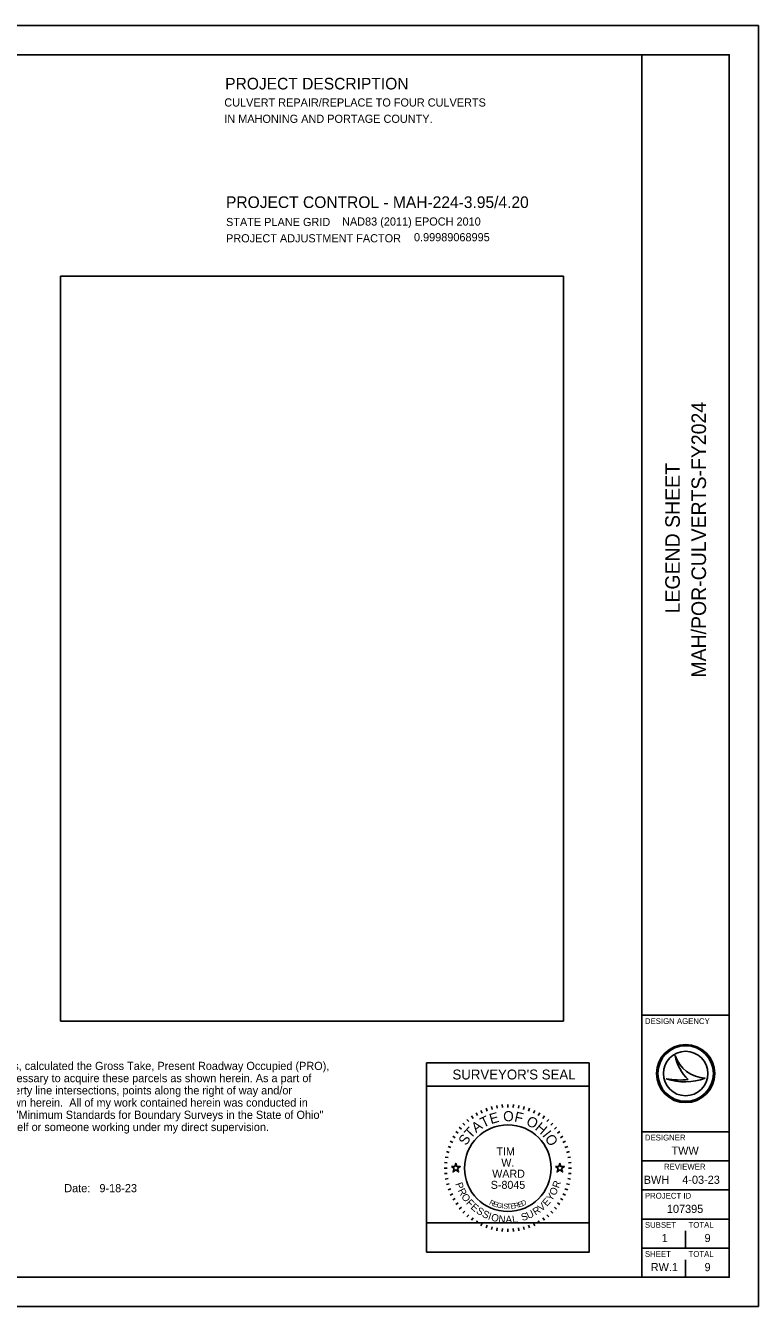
# Model space of a CAD drawing. Extents: x 0 to 34, y 0 to 22.
# Drawn here: x 21.41 to 34, y 0 to 22 of the extents above; entities that cross this region are included whole.
import ezdxf

# ---------------------------------------------------------------- set-up
doc = ezdxf.new("R2010")
doc.units = 0
for name, color, linetype in [('Default', 7, 'Continuous'), ('SH_Border', 7, 'Continuous'), ('SH_Cut_Line', 7, 'Continuous'), ('SH_Data', 7, 'Continuous'), ('SH_Text', 7, 'Continuous')]:
    doc.layers.add(name, color=color, linetype=linetype)

msp = doc.modelspace()

# ---------------------------------------------------------------- linework, layer by layer
at = {"layer": 'Default'}
for points in [[(28.725, 2.4), (28.783, 2.4), (28.801, 2.456), (28.82, 2.4), (28.878, 2.4), (28.831, 2.366), (28.849, 2.31), (28.801, 2.344), (28.754, 2.31), (28.772, 2.366)], [(30.512, 2.4), (30.571, 2.4), (30.589, 2.456), (30.607, 2.4), (30.666, 2.4), (30.618, 2.366), (30.636, 2.31), (30.589, 2.344), (30.542, 2.31), (30.56, 2.366)]]:
    msp.add_lwpolyline(points, close=True, dxfattribs=at)
at = {"layer": 'SH_Border'}
for p, q in [((32, 0.5), (32, 21.5)), ((32, 5), (33.5, 5)), ((32, 3), (33.5, 3)), ((32, 2.5), (33.5, 2.5)), ((32, 2), (33.5, 2)), ((32, 1.5), (33.5, 1.5)), ((32, 1), (33.5, 1))]:
    msp.add_line(p, q, dxfattribs=at)
msp.add_lwpolyline([(1.5, 21.5), (33.5, 21.5), (33.5, 0.5), (1.5, 0.5)], close=True, dxfattribs=at)
at = {"layer": 'SH_Cut_Line'}
msp.add_lwpolyline([(0, 0), (34, 0), (34, 22), (0, 22)], close=True, dxfattribs=at)
at = {"layer": 'SH_Data'}
for p, q in [((28.295, 0.933), (28.295, 4.183)), ((28.295, 4.183), (31.095, 4.183)), ((31.095, 4.183), (31.095, 0.933)), ((32.567, 4.31), (32.567, 4.31)), ((32.75, 4), (32.75, 4)), ((28.295, 3.783), (31.095, 3.783)), ((32.417, 3.91), (32.417, 3.91)), ((33.087, 3.919), (33.087, 3.919)), ((29.148, 3.322), (29.173, 3.279)), ((29.233, 3.366), (29.254, 3.321)), ((29.321, 3.403), (29.338, 3.356)), ((29.412, 3.432), (29.425, 3.383)), ((29.505, 3.452), (29.514, 3.403)), ((29.6, 3.465), (29.604, 3.415)), ((29.695, 3.469), (29.695, 3.419)), ((29.791, 3.465), (29.786, 3.415)), ((29.885, 3.452), (29.876, 3.403)), ((29.978, 3.432), (29.965, 3.383)), ((30.069, 3.403), (30.052, 3.356)), ((30.157, 3.366), (30.136, 3.321)), ((30.242, 3.322), (30.217, 3.279)), ((28.922, 3.148), (28.957, 3.113)), ((28.992, 3.213), (29.024, 3.175)), ((29.068, 3.271), (29.097, 3.23)), ((30.323, 3.271), (30.294, 3.23)), ((30.398, 3.213), (30.366, 3.175)), ((30.469, 3.148), (30.433, 3.113)), ((28.748, 2.922), (28.791, 2.897)), ((28.799, 3.002), (28.84, 2.974)), ((28.857, 3.078), (28.896, 3.046)), ((30.533, 3.078), (30.495, 3.046)), ((30.591, 3.002), (30.55, 2.974)), ((30.642, 2.922), (30.599, 2.897)), ((28.639, 2.658), (28.687, 2.645)), ((28.667, 2.749), (28.714, 2.732)), ((28.704, 2.837), (28.749, 2.816)), ((30.686, 2.837), (30.641, 2.816)), ((30.723, 2.749), (30.676, 2.732)), ((30.752, 2.658), (30.703, 2.645)), ((28.606, 2.47), (28.655, 2.466)), ((28.618, 2.565), (28.667, 2.556)), ((30.772, 2.565), (30.723, 2.556)), ((30.785, 2.47), (30.735, 2.466)), ((28.601, 2.375), (28.651, 2.375)), ((28.606, 2.28), (28.655, 2.284)), ((30.785, 2.28), (30.735, 2.284)), ((30.789, 2.375), (30.739, 2.375)), ((28.618, 2.185), (28.667, 2.194)), ((28.639, 2.092), (28.687, 2.105)), ((28.667, 2.001), (28.714, 2.018)), ((30.723, 2.001), (30.676, 2.018)), ((30.752, 2.092), (30.703, 2.105)), ((30.772, 2.185), (30.723, 2.194)), ((28.704, 1.913), (28.749, 1.934)), ((28.748, 1.828), (28.791, 1.853)), ((28.799, 1.748), (28.84, 1.776)), ((30.591, 1.748), (30.55, 1.776)), ((30.642, 1.828), (30.599, 1.853)), ((30.686, 1.913), (30.641, 1.934)), ((28.857, 1.672), (28.896, 1.704)), ((28.922, 1.602), (28.957, 1.637)), ((28.992, 1.537), (29.024, 1.575)), ((30.398, 1.537), (30.366, 1.575)), ((30.469, 1.602), (30.433, 1.637)), ((30.533, 1.672), (30.495, 1.704)), ((29.068, 1.479), (29.097, 1.52)), ((29.148, 1.428), (29.173, 1.471)), ((29.233, 1.384), (29.254, 1.429)), ((29.321, 1.347), (29.338, 1.394)), ((29.412, 1.319), (29.425, 1.367)), ((29.505, 1.298), (29.514, 1.347)), ((29.6, 1.285), (29.604, 1.335)), ((29.695, 1.281), (29.695, 1.331)), ((29.791, 1.285), (29.786, 1.335)), ((29.885, 1.298), (29.876, 1.347)), ((29.978, 1.319), (29.965, 1.367)), ((30.069, 1.347), (30.052, 1.394)), ((30.157, 1.384), (30.136, 1.429)), ((30.242, 1.428), (30.217, 1.471)), ((30.323, 1.479), (30.294, 1.52)), ((32.75, 1), (32.75, 1.3)), ((28.295, 0.933), (31.095, 0.933)), ((32.375, 0.675), (32.375, 0.675)), ((32.75, 0.5), (32.75, 0.8))]:
    msp.add_line(p, q, dxfattribs=at)
msp.add_lwpolyline([(28.295, 0.933), (28.295, 1.433), (31.095, 1.433), (31.095, 0.933)], close=True, dxfattribs=at)
for centre, radius in [((32.75, 4), 0.5), ((32.75, 4), 0.477), ((32.75, 4), 0.477), ((32.75, 4), 0.382), ((29.695, 2.375), 0.744)]:
    msp.add_circle(centre, radius, dxfattribs=at)
for centre, radius, start, end in [((33.116, 4.498), 0.58, 198.9257, 198.9319), ((33.347, 4.47), 0.796, 191.6379, 191.6421), ((33.116, 4.498), 0.58, 198.9319, 267.1657), ((33.347, 4.47), 0.796, 191.6421, 226.0947), ((32.739, 4.87), 1.013, 251.4576, 290.0832), ((32.648, 5.154), 1.266, 259.4964, 259.4995), ((32.739, 4.87), 1.013, 251.4527, 251.4576), ((32.648, 5.154), 1.266, 259.4995, 276.6672)]:
    msp.add_arc(centre, radius, start, end, dxfattribs=at)
at = {"layer": 'SH_Text'}
msp.add_lwpolyline([(22.011, 4.9), (30.651, 4.9), (30.651, 17.695), (22.011, 17.695)], close=True, dxfattribs=at)

# ---------------------------------------------------------------- texts
at = {"layer": 'SH_Data'}
for s, height, rotation, p in [('MAH/POR-CULVERTS-FY2024', 0.25, 90, (33.1, 10.8)), ('LEGEND SHEET', 0.25, 90, (32.65, 11.904)), ('E', 0.175, 15.7571, (29.406, 3.13)), ('O', 0.175, 359.7812, (29.614, 3.18)), ('F', 0.175, 347.4362, (29.797, 3.177)), ('T', 0.175, 46.4344, (29.056, 2.871)), ('A', 0.175, 36.4747, (29.149, 2.973)), ('T', 0.175, 25.7167, (29.272, 3.065)), ('O', 0.175, 332.2586, (29.995, 3.127)), ('H', 0.175, 319.9136, (30.149, 3.045)), ('S', 0.175, 57.1924, (28.98, 2.752)), ('I', 0.175, 308.367, (30.278, 2.935)), ('O', 0.175, 303.1491, (30.323, 2.886)), ('P', 0.125, 289.7431, (28.789, 2.105)), ('R', 0.125, 296.9802, (28.832, 1.991)), ('O', 0.125, 62.7428, (30.508, 1.892)), ('R', 0.125, 70.983, (30.571, 2.021)), ('O', 0.125, 304.7158, (28.887, 1.885)), ('F', 0.125, 312.956, (28.969, 1.77)), ('E', 0.125, 319.6885, (29.046, 1.688)), ('R', 0.0875, 334.487, (29.367, 1.756)), ('E', 0.0875, 341.04, (29.434, 1.725)), ('G', 0.0875, 347.4752, (29.497, 1.702)), ('I', 0.0875, 353.7858, (29.582, 1.684)), ('S', 0.0875, 356.8926, (29.615, 1.679)), ('T', 0.0875, 3.0061, (29.677, 1.673)), ('E', 0.0875, 6.0117, (29.744, 1.677)), ('R', 0.0875, 11.9184, (29.811, 1.684)), ('E', 0.0875, 17.6836, (29.882, 1.7)), ('D', 0.0875, 23.3052, (29.946, 1.721)), ('V', 0.125, 41.0316, (30.272, 1.626)), ('E', 0.125, 48.2687, (30.366, 1.709)), ('Y', 0.125, 55.5058, (30.445, 1.8)), ('S', 0.125, 326.9255, (29.14, 1.611)), ('S', 0.125, 334.1626, (29.24, 1.547)), ('I', 0.125, 341.3997, (29.344, 1.497)), ('O', 0.125, 345.1351, (29.397, 1.478)), ('N', 0.125, 353.3752, (29.528, 1.444)), ('A', 0.125, 1.1108, (29.657, 1.43)), ('L', 0.125, 8.3479, (29.778, 1.433)), ('S', 0.125, 18.3234, (29.946, 1.464)), ('U', 0.125, 25.5604, (30.049, 1.498)), ('R', 0.125, 33.296, (30.172, 1.559))]:
    msp.add_text(s, height=height, rotation=rotation, dxfattribs=at).set_placement(p)
for s, height, p in [('DESIGN AGENCY', 0.1, (32.05, 4.85)), ("SURVEYOR'S SEAL", 0.17, (28.743, 3.898)), ('DESIGNER', 0.1, (32.05, 2.85)), ('TIM ', 0.1375, (29.5, 2.594)), ('TWW', 0.14, (32.507, 2.605)), ('W.', 0.1375, (29.582, 2.402)), ('REVIEWER', 0.1, (32.378, 2.35)), ('WARD', 0.1375, (29.426, 2.21)), ('BWH', 0.14, (32.03, 2.105)), ('4-03-23', 0.14, (32.692, 2.105)), ('S-8045', 0.1375, (29.401, 2.019)), ('PROJECT ID', 0.1, (32.05, 1.85)), ('107395', 0.14, (32.428, 1.605)), ('SUBSET', 0.1, (32.05, 1.35)), ('TOTAL', 0.1, (32.8, 1.35)), ('1', 0.14, (32.339, 1.105)), ('9', 0.14, (33.075, 1.105)), ('SHEET', 0.1, (32.05, 0.85)), ('TOTAL', 0.1, (32.8, 0.85)), ('RW.1', 0.14, (32.15, 0.605)), ('9', 0.14, (33.075, 0.605))]:
    msp.add_text(s, height=height, dxfattribs=at).set_placement(p)
at = {"layer": 'SH_Text'}
for s, height, p in [('PROJECT DESCRIPTION', 0.2, (24.838, 20.903)), ('CULVERT REPAIR/REPLACE TO FOUR CULVERTS', 0.14, (24.823, 20.61)), ('IN MAHONING AND PORTAGE COUNTY.', 0.14, (24.823, 20.33)), ('PROJECT CONTROL - MAH-224-3.95/4.20', 0.2, (24.852, 18.867)), ('NAD83 (2011) EPOCH 2010      ', 0.14, (26.846, 18.565)), ('STATE PLANE GRID', 0.14, (24.853, 18.557)), ('PROJECT ADJUSTMENT FACTOR', 0.14, (24.853, 18.277)), ('0.99989068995', 0.14, (28.082, 18.296)), (', P. S.  have established the proposed property lines, calculated the Gross Take, Present Roadway Occupied (PRO),', 0.14, (16.95, 4.061)), ('Net Take and Net Residue; as well as prepared the legal descriptions necessary to acquire these parcels as shown herein. As a part of', 0.14, (15.154, 3.851)), ('this work I have set right of way monuments at the property corners, property line intersections, points along the right of way and/or', 0.14, (15.154, 3.641)), ('angle points on the right of way, Section Corners and other points as shown herein.  All of my work contained herein was conducted in', 0.14, (15.154, 3.431)), ('accordance with Ohio Administrative Code 4733-37 commonly known as "Minimum Standards for Boundary Surveys in the State of Ohio"', 0.14, (15.154, 3.221)), ('unless noted.  The words I and my as used herein are to mean either myself or someone working under my direct supervision.', 0.14, (15.154, 3.011)), (',                                   Date: ', 0.14, (20.2, 1.961)), ('9-18-23          ', 0.14, (22.677, 1.961))]:
    msp.add_text(s, height=height, dxfattribs=at).set_placement(p)

doc.saveas('drawing.dxf')
